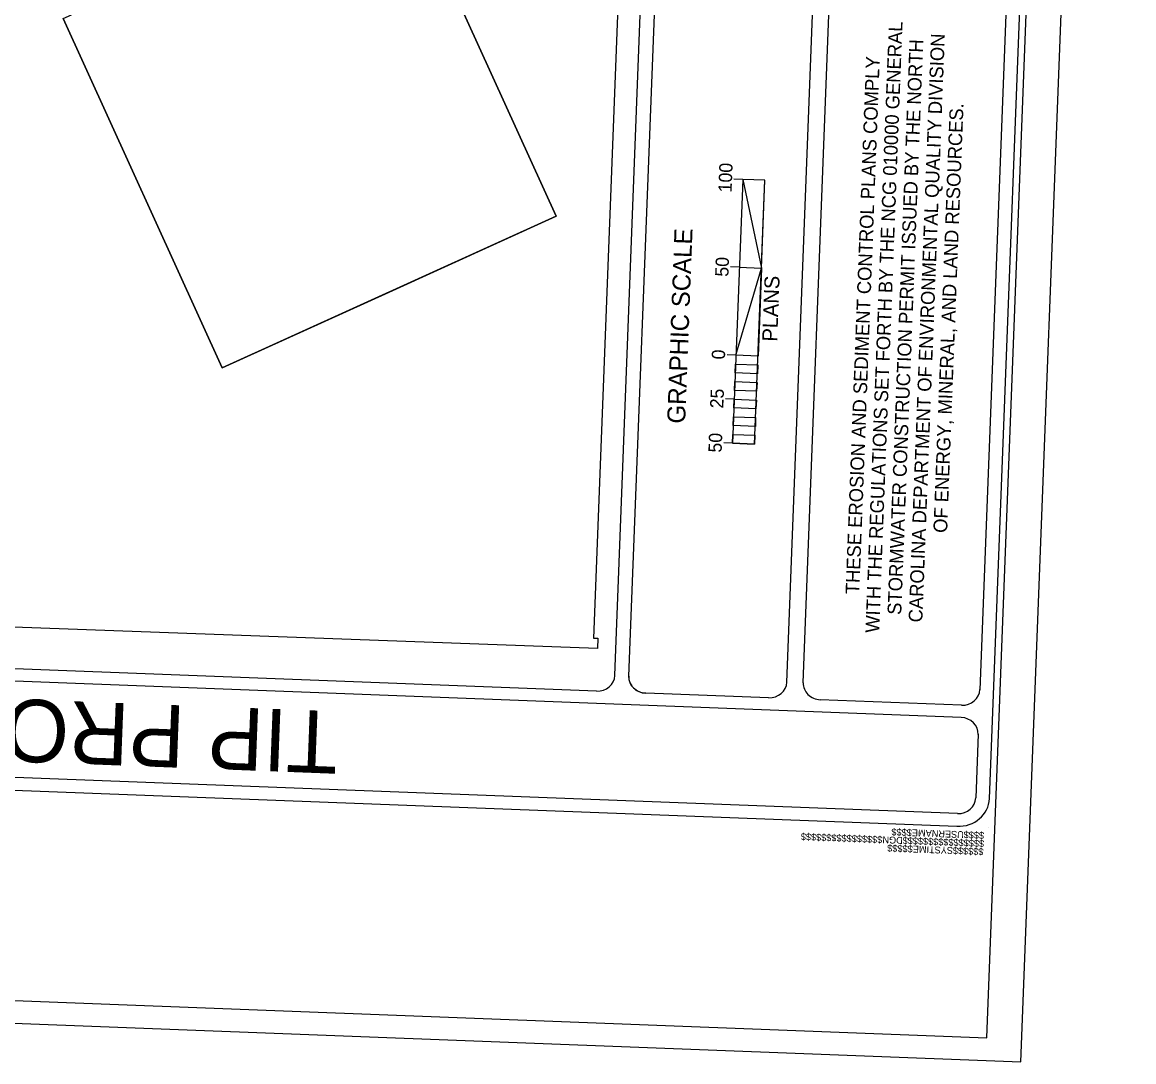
# Model space of a CAD drawing. Extents: x 1654773 to 2116434, y 680831 to 888488.
# Drawn here: x 2097383 to 2100565, y 682095 to 685073 of the extents above; entities that cross this region are included whole.
import ezdxf

# ---------------------------------------------------------------- set-up
doc = ezdxf.new("R2010")
doc.units = 0
for name, color, linetype in [('Default', 7, 'Continuous'), ('EC Title Sheet CELL', 7, 'Continuous'), ('Old_Level_38', 7, 'Continuous'), ('Scratch_Level_3', 7, 'Continuous'), ('Sheet Plot Border Inside CELL', 7, 'Continuous'), ('Sheet Plot Border Outside CELL', 7, 'Continuous')]:
    doc.layers.add(name, color=color, linetype=linetype)

msp = doc.modelspace()

# ---------------------------------------------------------------- linework, layer by layer
at = {"layer": 'Default'}
for p, q in [((2099445.5, 684622.6), (2099416.5, 683866.8)), ((2099445.5, 684622.6), (2099420.2, 684623.6)), ((2099508.7, 684620.2), (2099445.5, 684622.6)), ((2099479.7, 683864.4), (2099508.7, 684620.2)), ((2099435.8, 684370.7), (2099410.5, 684371.6)), ((2099435.8, 684370.7), (2099499.1, 684368.2)), ((2099426.2, 684118.7), (2099400.8, 684119.7)), ((2099421.3, 683992.8), (2099396, 683993.7)), ((2099416.5, 683866.8), (2099391.2, 683867.8)), ((2099391.2, 683867.8), (2099391.2, 683867.8)), ((2099416.5, 683866.8), (2099479.7, 683864.4)), ((2099416.5, 683866.8), (2099416.5, 683866.8))]:
    msp.add_line(p, q, dxfattribs=at)
at = {"layer": 'EC Title Sheet CELL'}
for p, q in [((2099079.7, 683201.5), (2099355.1, 690378.9)), ((2099200.8, 685330.5), (2099119, 683199.2)), ((2099572, 683182), (2099654, 685313.2)), ((2099618.9, 683180.2), (2099700.9, 685311.4)), ((2100206.4, 685292), (2100124.6, 683160.5)), ((2099027.3, 683155.9), (2094997, 683311.6)), ((2100070.9, 683080.4), (2094995.6, 683276.1)), ((2099519.7, 683137.5), (2099167.8, 683150.5)), ((2100072.2, 683115.8), (2099667.6, 683131.6)), ((2100113.7, 682850.7), (2100120.7, 683032.7)), ((2100060.4, 682806), (2094985.1, 682999.8)), ((2100161.3, 682931), (2100161.3, 682931)), ((2100148.8, 682765.2), (2100148.8, 682765.2)), ((2100144.4, 682163.3), (2100144.4, 682163.3)), ((2100242.3, 682094.5), (2100242.3, 682094.5))]:
    msp.add_line(p, q, dxfattribs=at)
for points in [[(2100152.1, 682848.2), (2100439.3, 690334.4)], [(2094983.7, 682963.5), (2100059, 682769.6)]]:
    msp.add_lwpolyline(points, dxfattribs=at)
msp.add_lwpolyline([(2098911.1, 684517.1), (2097955.4, 684082.2), (2097499.9, 685083.3), (2097523.8, 685094.2), (2097440.9, 685276.3), (2097563.6, 685332.1), (2097512.9, 685443.5), (2098323.2, 685809.3)], close=True, dxfattribs=at)
for centre, major_axis, start_param, end_param in [((2099029.2, 683203.1), (50.5, -1.9), 4.712389, 6.283185), ((2099169.5, 683197.2), (50.5, -1.9), 3.141593, 4.712389), ((2099169.7, 683197.7), (-50.5, 1.9), 6.283185, 7.853982), ((2099521.5, 683184.2), (50.5, -1.9), 4.712389, 6.283185), ((2099669.4, 683178.3), (-50.5, 1.9), 6.283185, 7.853982), ((2100074, 683162.5), (50.5, -1.9), 4.712389, 6.283185), ((2100069.2, 683034.2), (-50.5, 1.9), 3.141593, 4.712389), ((2100062.2, 682852.2), (89.9, -3.5), 4.712389, 6.283185), ((2100062.2, 682852.2), (50.5, -1.9), 4.712389, 6.283185)]:
    msp.add_ellipse(centre, major_axis=major_axis, ratio=0.923408, start_param=start_param, end_param=end_param, dxfattribs=at)
at = {"layer": 'Old_Level_38'}
msp.add_line((2099423.2, 684043.2), (2099486.5, 684040.7), dxfattribs=at)
for points in [[(2099445.5, 684622.6), (2099499.1, 684368.2), (2099508.7, 684620.2)], [(2099426.2, 684118.7), (2099499.1, 684368.2), (2099489.4, 684116.3)], [(2099424.2, 684068.3), (2099425.2, 684093.5), (2099488.4, 684091.1), (2099487.5, 684065.9)], [(2099422.3, 684018), (2099423.2, 684043.2), (2099486.5, 684040.7), (2099485.5, 684015.5)], [(2099420.3, 683967.6), (2099421.3, 683992.8), (2099484.6, 683990.3), (2099483.6, 683965.1)], [(2099418.4, 683917.2), (2099419.4, 683942.4), (2099482.6, 683939.9), (2099481.7, 683914.8)], [(2099416.5, 683866.8), (2099417.4, 683892), (2099480.7, 683889.6), (2099479.7, 683864.4)]]:
    msp.add_lwpolyline(points, close=True, dxfattribs=at)
at = {"layer": 'Scratch_Level_3'}
msp.add_lwpolyline([(2096808.4, 683360), (2096881.4, 685262.6), (2096363.6, 685282.4), (2096507.8, 689043.2), (2096159.7, 689056.5), (2096216.4, 690534.7), (2098809.6, 690435.2), (2098650.1, 686277.9), (2099132, 686259.4), (2099018.8, 683308.3), (2099031.1, 683307.9), (2099030, 683278.9)], close=True, dxfattribs=at)
msp.add_lwpolyline([(2097499.9, 685083.3), (2097955.4, 684082.2), (2098433.3, 684299.7), (2098911.1, 684517.1), (2098323.2, 685809.3)], dxfattribs=at)
at = {"layer": 'Sheet Plot Border Inside CELL'}
msp.add_lwpolyline([(2095168.6, 690692.8), (2094849, 682366.6), (2100144.4, 682163.3), (2100464, 690489.5)], close=True, dxfattribs=at)
at = {"layer": 'Sheet Plot Border Outside CELL'}
msp.add_lwpolyline([(2100242.3, 682094.5), (2100565.2, 690508.2), (2095069.1, 690719.1), (2094746.1, 682305.5)], close=True, dxfattribs=at)
msp.add_lwpolyline([(2100242.3, 682094.5), (2100565.2, 690508.2), (2095069.1, 690719.1), (2094746.1, 682305.5)], close=True, dxfattribs=at)

# ---------------------------------------------------------------- texts
at = {"layer": 'Default'}
msp.add_text('PLANS', height=43.04, rotation=87.802, dxfattribs=at).set_placement((2099544.2, 684157.1))
at = {"layer": 'EC Title Sheet CELL'}
for s, height, rotation, p in [('WITH THE REGULATIONS SET FORTH BY THE NCG 010000 GENERAL ', 39.375, 87.802, (2099836.1, 683322.8)), ('CAROLINA DEPARTMENT OF ENVIRONMENTAL QUALITY DIVISION', 39.375, 87.802, (2099959.7, 683352.7)), ('STORMWATER CONSTRUCTION PERMIT ISSUED BY THE NORTH', 39.375, 87.802, (2099899.3, 683374.4)), ('THESE EROSION AND SEDIMENT CONTROL PLANS COMPLY', 39.375, 87.802, (2099779.2, 683433.5)), ('OF ENERGY, MINERAL, AND LAND RESOURCES.', 39.375, 87.802, (2100030.7, 683609.2)), ('GRAPHIC SCALE', 51.579, 87.802, (2099280.6, 683922.1)), ('TIP PROJECT:  HL-0008I', 178.899, 177.802, (2098290, 683098.3)), ('$$$$$$$$$$$$$$$$DGN$$$$$$$$$$$$$$$$', 19.612, 177.802, (2100137.4, 682729.3)), ('$$$$USERNAME$$$$', 19.612, 177.802, (2100137.2, 682752.6)), ('$$$$$$SYSTIME$$$$$', 19.612, 177.802, (2100135.5, 682706))]:
    msp.add_text(s, height=height, rotation=rotation, dxfattribs=at).set_placement(p)
at = {"layer": 'Old_Level_38'}
for s, height, p in [('100', 37.98, (2099413.6, 684584.6)), ('50', 37.98, (2099404.4, 684343.1)), ('0', 38, (2099394.5, 684106.1)), ('25', 37.98, (2099389.9, 683965.8)), ('50', 37.98, (2099385, 683839.2))]:
    msp.add_text(s, height=height, rotation=87.802, dxfattribs=at).set_placement(p)

doc.saveas('drawing.dxf')
